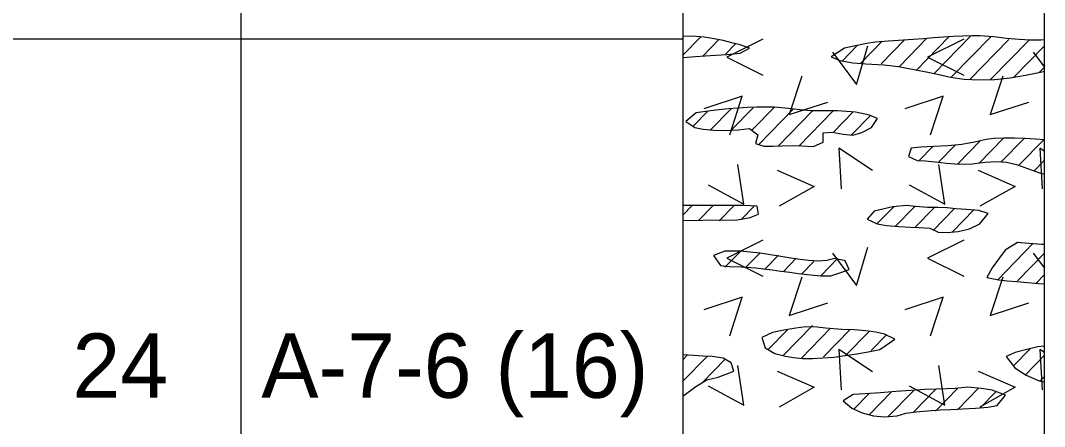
# Model space of a CAD drawing. Extents: x 0 to 0.83, y -0.65 to 1.27.
# Drawn here: x 0.7272 to 0.8333, y 0.8208 to 0.8629 of the extents above; entities that cross this region are included whole.
import ezdxf

# ---------------------------------------------------------------- set-up
doc = ezdxf.new("R2010")
doc.units = 0

msp = doc.modelspace()

# ---------------------------------------------------------------- linework, layer by layer
for points in [[(0, 0), (0.83333, 0), (0.83333, 1.275), (0, 1.275)], [(0, 0), (0.83333, 0), (0.83333, 1.275), (0, 1.275)], [(0, 0), (0.83333, 0), (0.83333, 1.275), (0, 1.275)], [(0, 0), (0.83333, 0), (0.83333, 1.275), (0, 1.275)], [(0, 0), (0.83333, 0), (0.83333, 1.275), (0, 1.275)], [(0.79583, 0.85904), (0.79715, 0.85915), (0.79814, 0.85922), (0.79922, 0.8593), (0.80039, 0.85938), (0.80179, 0.85951), (0.80275, 0.86002), (0.80179, 0.86036), (0.80091, 0.86058), (0.80003, 0.8608), (0.79909, 0.861), (0.79803, 0.86117), (0.79677, 0.86126), (0.79583, 0.86124)], [(0.82816, 0.85679), (0.82978, 0.85696), (0.83137, 0.85721), (0.8329, 0.85752), (0.83333, 0.85763), (0.83333, 0.86087), (0.83295, 0.86084), (0.83188, 0.86086), (0.83071, 0.86091), (0.82938, 0.86101), (0.82807, 0.86118), (0.82662, 0.8613), (0.82576, 0.8613), (0.82484, 0.86128), (0.82387, 0.86122), (0.82286, 0.86116), (0.82182, 0.86108), (0.82077, 0.86099), (0.81973, 0.86091), (0.81872, 0.86084), (0.81715, 0.86074), (0.81579, 0.86065), (0.81491, 0.86051), (0.81357, 0.86024), (0.8126, 0.86003), (0.81121, 0.85911), (0.8121, 0.85875), (0.81345, 0.8585), (0.81479, 0.85841), (0.81668, 0.85831), (0.81818, 0.85811), (0.81905, 0.85796), (0.82, 0.85778), (0.82107, 0.85757), (0.82225, 0.85732), (0.82357, 0.85702), (0.82501, 0.8568), (0.82656, 0.85673)], [(0.79708, 0.85181), (0.79794, 0.85163), (0.79904, 0.85152), (0.80028, 0.85149), (0.80156, 0.85154), (0.80274, 0.85169), (0.80361, 0.85103), (0.80338, 0.85014), (0.80422, 0.84986), (0.80517, 0.84985), (0.80613, 0.8499), (0.8072, 0.84993), (0.80818, 0.8499), (0.80939, 0.84983), (0.81037, 0.85029), (0.81038, 0.85124), (0.8113, 0.8513), (0.81244, 0.85112), (0.81346, 0.85101), (0.81438, 0.85127), (0.81539, 0.85181), (0.81601, 0.85272), (0.81517, 0.85309), (0.81374, 0.85337), (0.81285, 0.85346), (0.81187, 0.85352), (0.81, 0.85352), (0.8091, 0.85354), (0.808, 0.85362), (0.80678, 0.85377), (0.8053, 0.8539), (0.80443, 0.85392), (0.80349, 0.8539), (0.80251, 0.85386), (0.80152, 0.8538), (0.80054, 0.85372), (0.79959, 0.85363), (0.7987, 0.85353), (0.79722, 0.85331), (0.79614, 0.85243)], [(0.83241, 0.85059), (0.83129, 0.85065), (0.83017, 0.85069), (0.8291, 0.85069), (0.82811, 0.85065), (0.82728, 0.85057), (0.82608, 0.85027), (0.82476, 0.85004), (0.8233, 0.8499), (0.82183, 0.84982), (0.82051, 0.84976), (0.81951, 0.84966), (0.81922, 0.8488), (0.82013, 0.84838), (0.82097, 0.84833), (0.822, 0.84823), (0.82318, 0.8481), (0.82448, 0.84801), (0.82584, 0.84804), (0.82719, 0.8482), (0.82836, 0.84827), (0.8294, 0.84819), (0.83043, 0.84795), (0.83156, 0.84756), (0.83291, 0.84707), (0.83333, 0.847), (0.83333, 0.85052)], [(0.79583, 0.84218), (0.79676, 0.84217), (0.79792, 0.84219), (0.79882, 0.84223), (0.79992, 0.84218), (0.80151, 0.84223), (0.80282, 0.84248), (0.80367, 0.8428), (0.80354, 0.84364), (0.80216, 0.84373), (0.79583, 0.84373)], [(0.81822, 0.84153), (0.81944, 0.84147), (0.82033, 0.84143), (0.82145, 0.84137), (0.82229, 0.84095), (0.82324, 0.84091), (0.82438, 0.84101), (0.82555, 0.8413), (0.82662, 0.84181), (0.82749, 0.8429), (0.82651, 0.84321), (0.82524, 0.84331), (0.82413, 0.84337), (0.82324, 0.84348), (0.82226, 0.8435), (0.82121, 0.84352), (0.81995, 0.84361), (0.81902, 0.84373), (0.81761, 0.84359), (0.81566, 0.84314), (0.81496, 0.8423), (0.81598, 0.84182), (0.81695, 0.84164)], [(0.83305, 0.83968), (0.83171, 0.83979), (0.83054, 0.83989), (0.82925, 0.83907), (0.82857, 0.83816), (0.82792, 0.83727), (0.82735, 0.83624), (0.82858, 0.83602), (0.82945, 0.83592), (0.83045, 0.83582), (0.83155, 0.83573), (0.83272, 0.83563), (0.83333, 0.83558), (0.83333, 0.83967)], [(0.80066, 0.83738), (0.80188, 0.83737), (0.80339, 0.83724), (0.80423, 0.83714), (0.8051, 0.83703), (0.806, 0.83692), (0.80692, 0.8368), (0.80784, 0.83668), (0.80875, 0.83657), (0.81014, 0.83643), (0.81119, 0.83644), (0.81222, 0.83678), (0.81308, 0.83707), (0.81267, 0.83797), (0.8116, 0.83822), (0.81075, 0.83802), (0.80989, 0.83794), (0.80885, 0.83802), (0.80799, 0.83813), (0.80703, 0.83827), (0.806, 0.83843), (0.80492, 0.8386), (0.80384, 0.83876), (0.8028, 0.83889), (0.80182, 0.83898), (0.8002, 0.83899), (0.79901, 0.83852), (0.79974, 0.83748)], [(0.81233, 0.83087), (0.81063, 0.83099), (0.80977, 0.83112), (0.8086, 0.83113), (0.80755, 0.83099), (0.80632, 0.83079), (0.80513, 0.83054), (0.80403, 0.83002), (0.80436, 0.82896), (0.80536, 0.82839), (0.80647, 0.8281), (0.8073, 0.82795), (0.80824, 0.82787), (0.80926, 0.82786), (0.81035, 0.82791), (0.81149, 0.82801), (0.81267, 0.82816), (0.81386, 0.82834), (0.81506, 0.82856), (0.81625, 0.82879), (0.81783, 0.82987), (0.81673, 0.83037), (0.81585, 0.83057), (0.8148, 0.83073), (0.81361, 0.83083)], [(0.79583, 0.82396), (0.79719, 0.82495), (0.79831, 0.82565), (0.79951, 0.82592), (0.80111, 0.82653), (0.80086, 0.82741), (0.80002, 0.82789), (0.79889, 0.82808), (0.79791, 0.82811), (0.79694, 0.82817), (0.79583, 0.82825)], [(0.83265, 0.82906), (0.83136, 0.82875), (0.83028, 0.82847), (0.82934, 0.82808), (0.83026, 0.82688), (0.83142, 0.82612), (0.83279, 0.82554), (0.83333, 0.82544), (0.83333, 0.82915)], [(0.82537, 0.8249), (0.82408, 0.82475), (0.82319, 0.8247), (0.82214, 0.82467), (0.82091, 0.82464), (0.81947, 0.82454), (0.81792, 0.82442), (0.81632, 0.8243), (0.81475, 0.82421), (0.81348, 0.82411), (0.81247, 0.82347), (0.81337, 0.82271), (0.81444, 0.82221), (0.81561, 0.82192), (0.81675, 0.82181), (0.81807, 0.82192), (0.81896, 0.8222), (0.82003, 0.82234), (0.82157, 0.82247), (0.82253, 0.82252), (0.82362, 0.82258), (0.82483, 0.82264), (0.82618, 0.82271), (0.82745, 0.82282), (0.82842, 0.82299), (0.82927, 0.82405), (0.82791, 0.82457), (0.82679, 0.82476)]]:
    msp.add_lwpolyline(points, close=True)
for points in [[(0.75, 1.22083), (0.75, -0.64575)], [(0.75, 1.22083), (0.75, -0.64575)], [(0.79583, 1.22083), (0.79583, -0.64575)], [(0.83333, -0.64575), (0.83333, 1.13365)], [(0.79765, 0.86115), (0.79583, 0.85928)], [(0.81829, 0.85813), (0.82114, 0.86105)], [(0.82004, 0.85771), (0.82346, 0.86122)], [(0.82569, 0.86129), (0.82184, 0.85735)], [(0.82775, 0.86119), (0.8237, 0.85704)], [(0.725, 0.861), (0.75, 0.861)], [(0.75, 0.861), (0.79583, 0.861)], [(0.7996, 0.86094), (0.79786, 0.85915)], [(0.8013, 0.86046), (0.80027, 0.8594)], [(0.80412, 0.86096), (0.80038, 0.85909), (0.80412, 0.85721)], [(0.81134, 0.85962), (0.81384, 0.85625), (0.81503, 0.86025)], [(0.81392, 0.8603), (0.81235, 0.85869)], [(0.8143, 0.85848), (0.8165, 0.86073)], [(0.8164, 0.85841), (0.81879, 0.86086)], [(0.82496, 0.86096), (0.82121, 0.85909), (0.82496, 0.85721)], [(0.82964, 0.86092), (0.82557, 0.85674)], [(0.83173, 0.86085), (0.82774, 0.85676)], [(0.83333, 0.86027), (0.83012, 0.85698)], [(0.83217, 0.85962), (0.83333, 0.85806)], [(0.83281, 0.85752), (0.83333, 0.85806)], [(0.80818, 0.85713), (0.80687, 0.85313), (0.81087, 0.85444)], [(0.82901, 0.85713), (0.8277, 0.85313), (0.8317, 0.85444)], [(0.80069, 0.85105), (0.802, 0.85505), (0.798, 0.85374)], [(0.82152, 0.85105), (0.82284, 0.85505), (0.81884, 0.85374)], [(0.79871, 0.85155), (0.80085, 0.85374)], [(0.80083, 0.85151), (0.80311, 0.85385)], [(0.80534, 0.85392), (0.80299, 0.85151)], [(0.80367, 0.85), (0.80732, 0.85374)], [(0.79844, 0.85349), (0.79691, 0.85192)], [(0.80571, 0.84988), (0.80924, 0.85349)], [(0.81142, 0.85351), (0.80785, 0.84986)], [(0.81141, 0.85129), (0.81348, 0.85341)], [(0.81528, 0.85304), (0.81331, 0.85103)], [(0.82433, 0.84802), (0.82666, 0.85041)], [(0.82909, 0.85069), (0.82656, 0.8481)], [(0.82885, 0.84823), (0.83122, 0.85066)], [(0.83325, 0.85052), (0.83065, 0.84786)], [(0.81551, 0.84733), (0.81201, 0.84964), (0.81226, 0.84545)], [(0.82035, 0.84837), (0.82176, 0.84982)], [(0.82233, 0.84819), (0.82408, 0.84998)], [(0.83333, 0.84932), (0.83284, 0.84964), (0.83309, 0.84545)], [(0.83333, 0.8484), (0.83227, 0.84731)], [(0.79847, 0.84584), (0.80215, 0.84384), (0.80153, 0.84797)], [(0.80562, 0.84739), (0.80946, 0.8457), (0.80581, 0.84364)], [(0.8193, 0.84584), (0.82299, 0.84384), (0.82236, 0.84797)], [(0.82645, 0.84739), (0.83029, 0.8457), (0.82664, 0.84364)], [(0.79583, 0.8427), (0.79681, 0.8437)], [(0.79898, 0.84371), (0.79747, 0.84217)], [(0.80116, 0.84373), (0.79959, 0.84212)], [(0.80328, 0.84369), (0.80188, 0.84226)], [(0.8177, 0.84359), (0.81596, 0.84181)], [(0.81988, 0.84361), (0.81785, 0.84153)], [(0.82185, 0.84342), (0.81997, 0.84149)], [(0.824, 0.84341), (0.82178, 0.84113)], [(0.82601, 0.84325), (0.82378, 0.84097)], [(0.80412, 0.84013), (0.80038, 0.83825), (0.80412, 0.83638)], [(0.82496, 0.84013), (0.82121, 0.83825), (0.82496, 0.83638)], [(0.83217, 0.8398), (0.82844, 0.83599)], [(0.80188, 0.83903), (0.8002, 0.83731)], [(0.8038, 0.83879), (0.80237, 0.83732)], [(0.81134, 0.83879), (0.81384, 0.83541), (0.81503, 0.83941)], [(0.83333, 0.83879), (0.83052, 0.83591)], [(0.83217, 0.83879), (0.83333, 0.83723)], [(0.80575, 0.83857), (0.80429, 0.83708)], [(0.80758, 0.83824), (0.80627, 0.83689)], [(0.80941, 0.8379), (0.80816, 0.83662)], [(0.81188, 0.83821), (0.81016, 0.83646)], [(0.80818, 0.8363), (0.80687, 0.8323), (0.81087, 0.83361)], [(0.82901, 0.8363), (0.8277, 0.8323), (0.8317, 0.83361)], [(0.83333, 0.83657), (0.83245, 0.83567)], [(0.80069, 0.83022), (0.802, 0.83422), (0.798, 0.83291)], [(0.82152, 0.83022), (0.82284, 0.83422), (0.81884, 0.83291)], [(0.80465, 0.82875), (0.80667, 0.83083)], [(0.80626, 0.82819), (0.80928, 0.83128)], [(0.80809, 0.82785), (0.81111, 0.83095)], [(0.81041, 0.82802), (0.81318, 0.83085)], [(0.81264, 0.82809), (0.81518, 0.83069)], [(0.81536, 0.82867), (0.81699, 0.83033)], [(0.7963, 0.82821), (0.79583, 0.82772)], [(0.81551, 0.82649), (0.81201, 0.8288), (0.81226, 0.82462)], [(0.8301, 0.82709), (0.83184, 0.82887)], [(0.83131, 0.82612), (0.83333, 0.82819)], [(0.83333, 0.82848), (0.83284, 0.8288), (0.83309, 0.82462)], [(0.79834, 0.82808), (0.79583, 0.82551)], [(0.79786, 0.82538), (0.80023, 0.8278)], [(0.79847, 0.82501), (0.80215, 0.82301), (0.80153, 0.82713)], [(0.8193, 0.82501), (0.82299, 0.82301), (0.82236, 0.82713)], [(0.80562, 0.82655), (0.80946, 0.82487), (0.80581, 0.82281)], [(0.82645, 0.82655), (0.83029, 0.82487), (0.82664, 0.82281)], [(0.83285, 0.82549), (0.83333, 0.82598)], [(0.81519, 0.82427), (0.81354, 0.82258)], [(0.81514, 0.82201), (0.81748, 0.82441)], [(0.81709, 0.8218), (0.81974, 0.82451)], [(0.8197, 0.82225), (0.82203, 0.82465)], [(0.82202, 0.82241), (0.8243, 0.82475)], [(0.82431, 0.82255), (0.82644, 0.82474)], [(0.82663, 0.82271), (0.82834, 0.82447)]]:
    msp.add_lwpolyline(points)

# ---------------------------------------------------------------- texts
for s, p in [('24', (0.73255, 0.82378)), ('A-7-6 (16)', (0.75213, 0.82378))]:
    msp.add_text(s, height=0.006667).set_placement(p)

doc.saveas('drawing.dxf')
